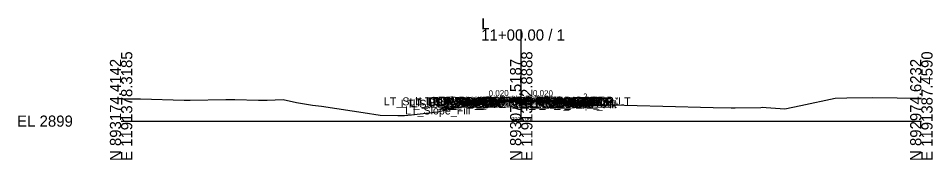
# Model space of a CAD drawing. Extents: x -26 to 203, y -10 to 7027.
# Drawn here: x -25.7 to 202.8, y 1990.3 to 2025.8 of the extents above; entities that cross this region are included whole.
import ezdxf

# ---------------------------------------------------------------- set-up
doc = ezdxf.new("R2010")
doc.units = 0
for name, color, linetype in [('Default', 7, 'Continuous'), ('Exist CMT Pavement', 7, 'Continuous'), ('Exist Cross Section Cell', 7, 'Continuous'), ('Exist XS Center Line Elevation Label', 7, 'Continuous'), ('Exist XS Ground Line', 7, 'Continuous'), ('Prop CMT Concrete Structures', 7, 'Continuous'), ('Prop CMT Pvmt Course 1', 7, 'Continuous'), ('Prop CMT Pvmt Course 2', 7, 'Continuous'), ('Prop CMT Pvmt Course 2 Wedge', 7, 'Continuous'), ('Prop CMT Pvmt Course 3', 7, 'Continuous'), ('Prop CMT Pvmt Course 3 Wedge', 7, 'Continuous'), ('Prop CMT Pvmt Surface', 7, 'Continuous'), ('Prop CMT Pvmt Surface Shoulder', 7, 'Continuous'), ('Prop CMT Pvmt Wedge Surface 3', 7, 'Continuous'), ('Prop CMT Shld Paved Course 1', 7, 'Continuous'), ('Prop CMT Shld Paved Course 2', 7, 'Continuous'), ('Prop CMT Shld Paved Course 3', 7, 'Continuous'), ('Prop CMT Slope Grass', 7, 'Continuous'), ('Prop CMT Subgrade Earthwork', 7, 'Continuous'), ('Scratch_Level_6', 7, 'Continuous')]:
    doc.layers.add(name, color=color, linetype=linetype)

msp = doc.modelspace()

# ---------------------------------------------------------------- linework, layer by layer
at = {"layer": 'Exist CMT Pavement'}
for points in [[(89, 2004.94), (86.79, 2004.9), (86.57, 2004.69)], [(86.57, 2004.69), (89, 2004.73)], [(89, 2004.73), (89, 2004.94)], [(100, 2005.06), (91.15, 2005.02)], [(91.15, 2005.02), (95.57, 2005.05)], [(95.57, 2005.05), (100, 2005.06)], [(104.67, 2004.9), (100, 2005.06)], [(100, 2005.06), (109.34, 2004.74)], [(109.34, 2004.74), (104.67, 2004.9)], [(111, 2004.94), (113.21, 2004.9), (113.43, 2004.69)], [(111, 2004.73), (111, 2004.94)], [(113.43, 2004.69), (111, 2004.73)]]:
    msp.add_lwpolyline(points, dxfattribs=at)
at = {"layer": 'Exist Cross Section Cell'}
for p, q in [((100, 2000), (100, 2023)), ((0, 2000), (100, 2000)), ((100, 2000), (200, 2000))]:
    msp.add_line(p, q, dxfattribs=at)
at = {"layer": 'Exist XS Center Line Elevation Label'}
for points in [[(100, 2005.16), (91.15, 2004.99)], [(100, 2005.16), (109.34, 2004.98)]]:
    msp.add_lwpolyline(points, dxfattribs=at)
at = {"layer": 'Exist XS Ground Line'}
for points in [[(100, 2005.25), (91.15, 2005.07)], [(100, 2005.25), (109.34, 2005.06)]]:
    msp.add_lwpolyline(points, dxfattribs=at)
at = {"layer": 'Prop CMT Concrete Structures'}
for points in [[(100, 2005.37), (89, 2005.15)], [(100, 2005.37), (111, 2005.15)]]:
    msp.add_lwpolyline(points, dxfattribs=at)
at = {"layer": 'Prop CMT Pvmt Course 1'}
for points in [[(100, 2005.37), (89, 2005.15)], [(89, 2005.15), (89, 2004.94)], [(89, 2004.94), (91.15, 2004.99)], [(91.15, 2004.99), (89, 2004.94)], [(89, 2004.94), (89, 2004.73)], [(89, 2004.73), (91.15, 2004.78)], [(91.15, 2005.07), (100, 2005.25)], [(91.15, 2004.99), (91.15, 2005.07)], [(91.15, 2004.78), (91.15, 2004.99)], [(100, 2005.16), (100, 2005.37)], [(100, 2005.37), (111, 2005.15)], [(100, 2005.16), (100, 2005.37)], [(100, 2005.25), (100, 2005.16), (100, 2005.16)], [(109.34, 2005.06), (100, 2005.25)], [(100, 2005.25), (100, 2005.16), (100, 2005.16)], [(109.34, 2004.98), (109.34, 2005.06)], [(111, 2004.94), (109.34, 2004.98)], [(109.34, 2004.77), (109.34, 2004.98)], [(109.34, 2004.98), (111, 2004.94)], [(111, 2004.73), (109.34, 2004.77)], [(111, 2005.15), (111, 2004.94)], [(111, 2004.94), (111, 2004.73)]]:
    msp.add_lwpolyline(points, dxfattribs=at)
at = {"layer": 'Prop CMT Pvmt Course 2'}
for points in [[(100, 2004.95), (91.15, 2004.78)], [(100, 2004.95), (109.34, 2004.77)]]:
    msp.add_lwpolyline(points, dxfattribs=at)
at = {"layer": 'Prop CMT Pvmt Course 3'}
for points in [[(91.15, 2004.78), (89, 2004.73)], [(89, 2004.73), (89, 2004.4)], [(89, 2004.4), (91.15, 2004.44)], [(91.15, 2004.44), (91.15, 2004.78)], [(109.34, 2004.77), (111, 2004.73)], [(109.34, 2004.43), (109.34, 2004.77)], [(111, 2004.4), (109.34, 2004.43)], [(111, 2004.73), (111, 2004.4)]]:
    msp.add_lwpolyline(points, dxfattribs=at)
at = {"layer": 'Prop CMT Pvmt Course 3 Wedge'}
for p, q in [((0, 2005.63), (2.96, 2005.62)), ((2.96, 2005.62), (4.86, 2005.61)), ((4.86, 2005.61), (15.76, 2005.25)), ((15.76, 2005.25), (16.56, 2005.27)), ((16.56, 2005.27), (17.28, 2005.29)), ((17.28, 2005.29), (26.15, 2005.4)), ((26.15, 2005.4), (27.9, 2005.43)), ((27.9, 2005.43), (28.43, 2005.41)), ((28.43, 2005.41), (34.35, 2005.27)), ((34.35, 2005.27), (36.52, 2005.28)), ((36.52, 2005.28), (40.49, 2005.39)), ((40.49, 2005.39), (43.81, 2004.71)), ((43.81, 2004.71), (47.82, 2004.04)), ((85.06, 2003.68), (87.49, 2004.23)), ((87.49, 2004.23), (90.06, 2004.79)), ((90.06, 2004.79), (91.15, 2005.02)), ((91.15, 2005.02), (99.06, 2005.07)), ((99.06, 2005.07), (99.7, 2005.07)), ((99.7, 2005.07), (100, 2005.06)), ((100, 2005.06), (100.47, 2005.05)), ((100.47, 2005.05), (109.34, 2004.74)), ((109.34, 2004.74), (110.03, 2004.68)), ((110.03, 2004.68), (113.8, 2004.29)), ((113.8, 2004.29), (117.52, 2004.17)), ((169.89, 2003.92), (178.45, 2005.78)), ((178.45, 2005.78), (181.37, 2005.88)), ((181.37, 2005.88), (187.89, 2005.94)), ((187.89, 2005.94), (200, 2005.73)), ((47.82, 2004.04), (50.07, 2003.71)), ((50.07, 2003.71), (57.76, 2002.56)), ((57.76, 2002.56), (60.47, 2002.15)), ((60.47, 2002.15), (64.78, 2001.46)), ((72.61, 2001.59), (79.06, 2002.37)), ((79.06, 2002.37), (85.06, 2003.68)), ((117.52, 2004.17), (122.55, 2004.05)), ((122.55, 2004.05), (135.42, 2003.74)), ((135.42, 2003.74), (148, 2003.42)), ((148, 2003.42), (152.47, 2003.35)), ((152.47, 2003.35), (153.43, 2003.29)), ((153.43, 2003.29), (159.88, 2003.45)), ((159.88, 2003.45), (160.28, 2003.47)), ((160.28, 2003.47), (161.21, 2003.4)), ((161.21, 2003.4), (165.9, 2003.07)), ((165.9, 2003.07), (167.85, 2003.5)), ((167.85, 2003.5), (169.89, 2003.92)), ((64.78, 2001.46), (69.14, 2001.4)), ((69.14, 2001.4), (70.86, 2001.37)), ((70.86, 2001.37), (72.61, 2001.59))]:
    msp.add_line(p, q, dxfattribs=at)
at = {"layer": 'Prop CMT Pvmt Surface'}
for points in [[(87, 2005.11), (85, 2004.95), (80.43, 2002.67)], [(113, 2005.11), (115, 2004.95), (116.5, 2004.2)]]:
    msp.add_lwpolyline(points, dxfattribs=at)
at = {"layer": 'Prop CMT Pvmt Surface Shoulder'}
for points in [[(89, 2005.15), (87, 2005.11)], [(111, 2005.15), (113, 2005.11)]]:
    msp.add_lwpolyline(points, dxfattribs=at)
at = {"layer": 'Prop CMT Shld Paved Course 1'}
for points in [[(89, 2005.15), (87, 2005.11), (86.79, 2004.9)], [(86.79, 2004.9), (89, 2004.94)], [(89, 2004.94), (89, 2005.15)], [(89, 2004.94), (89, 2005.15)], [(91.15, 2004.99), (89, 2004.94)], [(100, 2005.25), (91.15, 2005.07)], [(91.15, 2005.07), (91.15, 2004.99)], [(100, 2005.25), (109.34, 2005.06)], [(109.34, 2005.06), (109.34, 2004.98)], [(109.34, 2004.98), (111, 2004.94)], [(111, 2005.15), (113, 2005.11), (113.21, 2004.9)], [(111, 2004.94), (111, 2005.15)], [(111, 2004.94), (111, 2005.15)], [(113.21, 2004.9), (111, 2004.94)]]:
    msp.add_lwpolyline(points, dxfattribs=at)
at = {"layer": 'Prop CMT Shld Paved Course 2'}
for points in [[(100, 2005.16), (89, 2004.94)], [(89, 2004.94), (89, 2005.15)], [(100, 2005.16), (111, 2004.94)], [(111, 2004.94), (111, 2005.15)]]:
    msp.add_lwpolyline(points, dxfattribs=at)
at = {"layer": 'Prop CMT Shld Paved Course 3'}
for points in [[(89, 2004.73), (89, 2005.15)], [(100, 2004.95), (89, 2004.73)], [(100, 2004.95), (111, 2004.73)], [(111, 2004.73), (111, 2005.15)]]:
    msp.add_lwpolyline(points, dxfattribs=at)
at = {"layer": 'Prop CMT Slope Grass'}
for points in [[(89, 2004.73), (86.57, 2004.69), (86.07, 2004.68), (85.73, 2004.34)], [(85.73, 2004.34), (89, 2004.4)], [(89, 2004.4), (89, 2004.73)], [(111, 2004.73), (113.43, 2004.69), (113.93, 2004.68), (114.27, 2004.34)], [(111, 2004.4), (111, 2004.73)], [(114.27, 2004.34), (111, 2004.4)]]:
    msp.add_lwpolyline(points, dxfattribs=at)
at = {"layer": 'Prop CMT Subgrade Earthwork'}
for points in [[(85.73, 2004.34), (85.11, 2004.96)], [(89, 2004.4), (85.73, 2004.34)], [(91.15, 2004.44), (89, 2004.4)], [(91.15, 2004.44), (91.16, 2005.02)], [(109.34, 2004.43), (109.33, 2004.74)], [(109.34, 2004.43), (111, 2004.4)], [(111, 2004.4), (114.27, 2004.34)], [(114.27, 2004.34), (114.89, 2004.96)]]:
    msp.add_lwpolyline(points, dxfattribs=at)

# ---------------------------------------------------------------- texts
at = {"layer": 'Default'}
msp.add_text('-', height=0.0001, dxfattribs=at).set_placement((0, 2000))
at = {"layer": 'Exist Cross Section Cell'}
for s, p in [('L', (90, 2023)), ('11+00.00 / 1', (90, 2020.2)), ('EL 2899', (-26, 1998.6))]:
    msp.add_text(s, height=2.8, dxfattribs=at).set_placement(p)
for s, p in [('E 1191378.3185', (2.8, 1990)), ('E 1191382.8888', (102.8, 1990)), ('E 1191387.4590', (202.8, 1990)), ('N 893174.4142', (0, 1990)), ('N 893074.5187', (100, 1990)), ('N 892974.6232', (200, 1990))]:
    msp.add_text(s, height=2.8, rotation=90, dxfattribs=at).set_placement(p)
at = {"layer": 'Prop CMT Pvmt Course 2 Wedge'}
for s, p in [('LT_Sub_Trench_Out_DLT', (65.68, 2003.96)), ('LT_Sub_Trench_Out', (69.94, 2003.34)), ('LT_PS3_Shelf_Out', (72.06, 2003.68)), ('LT_GS_OS_CTL', (74.37, 2003.95)), ('LT_PV_Sub_Tie_Out', (76.11, 2004.02)), ('LT_PS3_OEOP', (76.81, 2003.69)), ('LT_PS2_OEOP', (77.02, 2003.9)), ('LT_PS1_OEOP', (77.8, 2004.11)), ('LT_PV_OEEOP_EG', (78.69, 2004.02)), ('LT_Sub_OEOT', (79.08, 2003.4)), ('LT_PV2_OEOT', (79.17, 2003.94)), ('LT_PV3_OEOT', (79.17, 2003.73)), ('LT_PV1_OEOT', (79.74, 2004.15)), ('LT_Sub_OEEOP', (80.36, 2003.44)), ('LT_PV2_OEEOP', (80.46, 2003.99)), ('LT_PV3_OEEOP', (80.46, 2003.78)), ('LT_PV1_OEEOP', (81.02, 2004.07)), ('LT_PV_EG_TestPt', (81.98, 2004.05)), ('RT_PV_IEEOP_EG', (88.14, 2004.06)), ('LT_PV_IEEOP_EG', (88.19, 2004.06)), ('RT_PV2_IEEOP', (89.91, 2004.16)), ('RT_PV3_IEEOP', (89.91, 2003.95)), ('LT_PV2_IEEOP', (89.95, 2004.16)), ('LT_PV3_IEEOP', (89.95, 2003.95)), ('RT_PV1_IEEOP', (90.47, 2004.25)), ('LT_PV1_IEEOP', (90.52, 2004.25)), ('RT_PV_EG_TestPt', (91.03, 2003.9)), ('PV2_PGL', (93.91, 2004.16)), ('RT_PV_Sub_Tie_Out', (94.22, 2003.74)), ('PV1_PGL', (94.47, 2004.37)), ('RT_Sub_Trench_Out_DLT', (95.41, 2003.96)), ('RT_PV_OEEOP_EG', (96.84, 2003.74)), ('RT_Sub_Trench_Out', (98.42, 2003.34)), ('RT_Sub_OEEOP', (98.51, 2003.43)), ('RT_PV2_OEEOP', (98.6, 2003.98)), ('RT_PV3_OEEOP', (98.6, 2003.77)), ('RT_PV1_OEEOP', (99.17, 2004.06)), ('RT_PS3_Shelf_Out', (99.86, 2003.68)), ('RT_Sub_OEOT', (101.03, 2003.4)), ('RT_PV2_OEOT', (101.13, 2003.94)), ('RT_PV3_OEOT', (101.13, 2003.73)), ('RT_PV1_OEOT', (101.69, 2004.15)), ('RT_PS2_OEOP', (103.4, 2003.9)), ('RT_PS3_OEOP', (103.61, 2003.69)), ('RT_PS1_OEOP', (103.76, 2004.11)), ('RT_GS_OS_CTL', (104.32, 2003.95)), ('RT_Slope_Fill', (106.97, 2003.2)), ('LT_Slope_Fill', (70.95, 2001.67))]:
    msp.add_text(s, height=2, dxfattribs=at).set_placement(p)
at = {"layer": 'Prop CMT Pvmt Surface Shoulder'}
for rotation, p in [(1.1458, (91.86, 2006.21)), (358.8542, (102.9, 2006.31))]:
    msp.add_text('0.020', height=1.5, rotation=rotation, dxfattribs=at).set_placement(p)
at = {"layer": 'Prop CMT Pvmt Wedge Surface 3'}
for rotation, p in [(333.4349, (115.02, 2005.78)), (26.5651, (81.32, 2003.95))]:
    msp.add_text('2:1', height=1.5, rotation=rotation, dxfattribs=at).set_placement(p)
at = {"layer": 'Scratch_Level_6'}
msp.add_text('2904.06', height=1, dxfattribs=at).set_placement((97.51, 2000.06))

doc.saveas('drawing.dxf')
